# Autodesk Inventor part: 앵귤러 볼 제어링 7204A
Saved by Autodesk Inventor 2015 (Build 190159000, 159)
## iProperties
Created: 2024-12
Part Number: 앵귤러 볼 제어링 7204A
Material: 일반
Document SubType Name: Modeling
Designer: 102-5
Density: 1 g/cm^3
Appearance: 기본값
Author: 102-5
Author: jhkim
Description: 앵귤러 콘택트 볼 베어링
Creation Date: 2024-11-28
Sending System: Autodesk Inventor 2025
Preprocessor: ST-DEVELOPER v20
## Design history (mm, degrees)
node "앵귤러 볼 제어링 7204A1"
body "Solid1"
node "Solid1_1"
node "Solid1_2"
node "Solid1_3"
node "Solid1_4"
node "Solid1_5"
node "Solid1_6"
node "Solid1_7"
node "Solid1_8"
node "Solid1_9"
node "기준1"
node "기준2"
node "기준3"
node "기준4"
node "기준5"
node "기준6"
node "기준7"
node "기준8"
node "기준9"
node "기준10"
